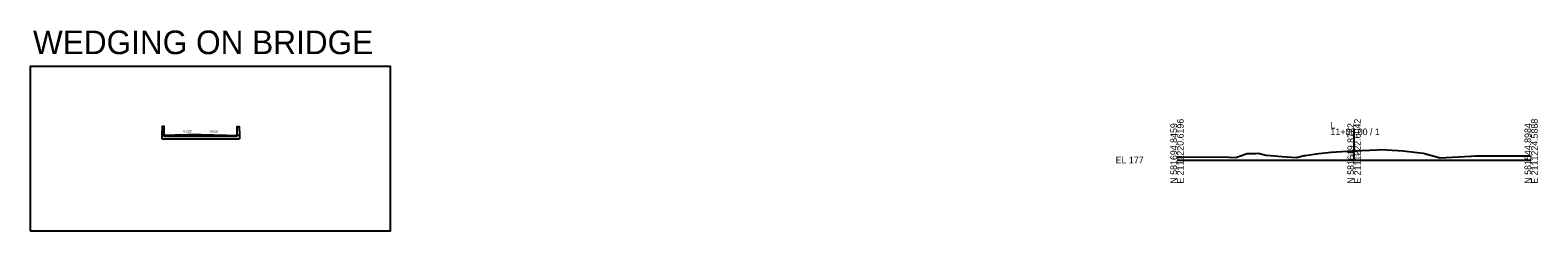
# Model space of a CAD drawing. Extents: x -486 to 1153, y -333 to 9539.
# Drawn here: x -486 to 153, y -30 to 55 of the extents above; entities that cross this region are included whole.
import ezdxf

# ---------------------------------------------------------------- set-up
doc = ezdxf.new("R2010")
doc.units = 0
for name, color, linetype in [('Default', 7, 'Continuous'), ('Exist Cross Section Cell', 7, 'Continuous'), ('Exist XS Center Line Elevation Label', 7, 'Continuous'), ('Exist XS Ground Line', 7, 'Continuous'), ('Prop CMT Concrete Structures', 7, 'Continuous'), ('Prop XS SE Text', 7, 'Continuous'), ('Scratch_Level_1', 7, 'Continuous'), ('Scratch_Level_2', 7, 'Continuous')]:
    doc.layers.add(name, color=color, linetype=linetype)

msp = doc.modelspace()

# ---------------------------------------------------------------- linework, layer by layer
at = {"layer": 'Exist Cross Section Cell'}
for p, q in [((75, 0), (75, 13.35)), ((0, 0), (75, 0)), ((75, 0), (150, 0))]:
    msp.add_line(p, q, dxfattribs=at)
at = {"layer": 'Exist XS Ground Line'}
for p, q in [((0, 1.34), (0.82, 1.32)), ((0.82, 1.32), (1.9, 1.31)), ((1.9, 1.31), (21.9, 1.21)), ((21.9, 1.21), (24.85, 1.15)), ((24.85, 1.15), (29.65, 2.8)), ((29.65, 2.8), (33.28, 2.78)), ((33.28, 2.78), (34.43, 2.89)), ((34.43, 2.89), (37.64, 2.1)), ((37.64, 2.1), (37.96, 2.12)), ((37.96, 2.12), (46.24, 1.36)), ((46.24, 1.36), (50.67, 1.13)), ((50.67, 1.13), (53.85, 1.86)), ((53.85, 1.86), (54.22, 1.91)), ((54.22, 1.91), (60.14, 2.84)), ((60.14, 2.84), (65.31, 3.36)), ((65.31, 3.36), (74.2, 3.84)), ((74.2, 3.84), (74.52, 3.86)), ((74.52, 3.86), (75, 3.88)), ((75, 3.88), (84.73, 4.29)), ((84.73, 4.29), (86.34, 4.45)), ((86.34, 4.45), (93.48, 4.09)), ((93.48, 4.09), (95.8, 3.92)), ((95.8, 3.92), (104.24, 2.93)), ((104.24, 2.93), (104.78, 2.75)), ((104.78, 2.75), (111.51, 0.97)), ((111.51, 0.97), (124.37, 1.67)), ((124.37, 1.67), (124.77, 1.68)), ((124.77, 1.68), (126.47, 1.8)), ((126.47, 1.8), (126.82, 1.83)), ((126.82, 1.83), (148.6, 1.72)), ((148.6, 1.72), (148.9, 1.72)), ((148.9, 1.72), (149.24, 1.72)), ((149.24, 1.72), (150, 1.68))]:
    msp.add_line(p, q, dxfattribs=at)
at = {"layer": 'Prop CMT Concrete Structures'}
msp.add_line((-430.07, 8.93), (-397.07, 8.93), dxfattribs=at)
for points in [[(-428.99, 10.45), (-429.07, 14.26), (-429.9, 14.26), (-429.99, 10.43)], [(-398.15, 10.45), (-398.07, 14.26), (-397.24, 14.26), (-397.15, 10.43)], [(-413.57, 10.76), (-424.57, 10.54), (-430.07, 10.43)], [(-430.07, 10.43), (-430.07, 8.93)], [(-429.99, 10.43), (-428.99, 10.45)], [(-413.57, 10.76), (-402.57, 10.54), (-397.07, 10.43)], [(-397.15, 10.43), (-398.15, 10.45)], [(-397.07, 10.43), (-397.07, 8.93)]]:
    msp.add_lwpolyline(points, dxfattribs=at)
at = {"layer": 'Scratch_Level_1'}
for p, q in [((-424.57, 10.33), (-428.99, 10.24)), ((-428.99, 10.24), (-428.99, 10.16)), ((-428.99, 10.24), (-428.99, 10.16)), ((-428.99, 10.16), (-418.77, 10.16)), ((-428.99, 10.16), (-418.77, 10.16)), ((-418.77, 10.45), (-424.57, 10.33)), ((-418.77, 10.16), (-418.77, 10.45)), ((-418.77, 10.16), (-418.77, 10.45)), ((-408.37, 10.16), (-408.37, 10.45)), ((-408.37, 10.45), (-408.37, 10.16)), ((-398.15, 10.16), (-408.37, 10.16)), ((-408.37, 10.16), (-398.15, 10.16)), ((-398.15, 10.24), (-398.15, 10.16)), ((-398.15, 10.16), (-398.15, 10.24))]:
    msp.add_line(p, q, dxfattribs=at)
for points in [[(-485.78, -29.96), (-333.2, -29.96), (-333.2, 39.63), (-485.78, 39.63), (-485.78, -29.96)], [(-398.15, 10.24), (-402.57, 10.33), (-408.37, 10.45)]]:
    msp.add_lwpolyline(points, dxfattribs=at)
at = {"layer": 'Scratch_Level_2'}
for p, q in [((-418.77, 10.45), (-418.77, 10.16)), ((-413.57, 10.16), (-418.77, 10.16)), ((-418.77, 10.16), (-413.57, 10.16)), ((-413.57, 10.55), (-413.57, 10.55)), ((-408.37, 10.45), (-413.57, 10.55)), ((-408.37, 10.16), (-413.57, 10.16)), ((-413.57, 10.16), (-408.37, 10.16)), ((-408.37, 10.16), (-408.37, 10.45))]:
    msp.add_line(p, q, dxfattribs=at)
msp.add_lwpolyline([(-413.57, 10.55), (-413.57, 10.55), (-418.77, 10.45)], dxfattribs=at)

# ---------------------------------------------------------------- texts
at = {"layer": 'Default'}
for s, height, p in [('-', 0.0001, (0, 0)), ('180.88', 1, (72.98, 1.88))]:
    msp.add_text(s, height=height, dxfattribs=at).set_placement(p)
at = {"layer": 'Exist Cross Section Cell'}
for s, p in [('N 581694.8459', (0, -10)), ('E 2111220.6196', (2.8, -10)), ('N 581619.8722', (75, -10)), ('E 2111222.6042', (77.8, -10)), ('N 581544.8984', (150, -10)), ('E 2111224.5888', (152.8, -10))]:
    msp.add_text(s, height=2.8, rotation=90, dxfattribs=at).set_placement(p)
for s, p in [('11+00.00 / 1', (65, 10.55)), ('L', (65, 13.35)), ('EL 177', (-26, -1.4))]:
    msp.add_text(s, height=2.8, dxfattribs=at).set_placement(p)
at = {"layer": 'Exist XS Center Line Elevation Label'}
msp.add_text('WEDGING ON BRIDGE', height=10, dxfattribs=at).set_placement((-484.6, 44.83))
at = {"layer": 'Prop XS SE Text'}
for rotation, p in [(1.14576, (-420.84, 11.61)), (358.85424, (-409.8, 11.68))]:
    msp.add_text('0.020', height=1, rotation=rotation, dxfattribs=at).set_placement(p)

doc.saveas('drawing.dxf')
